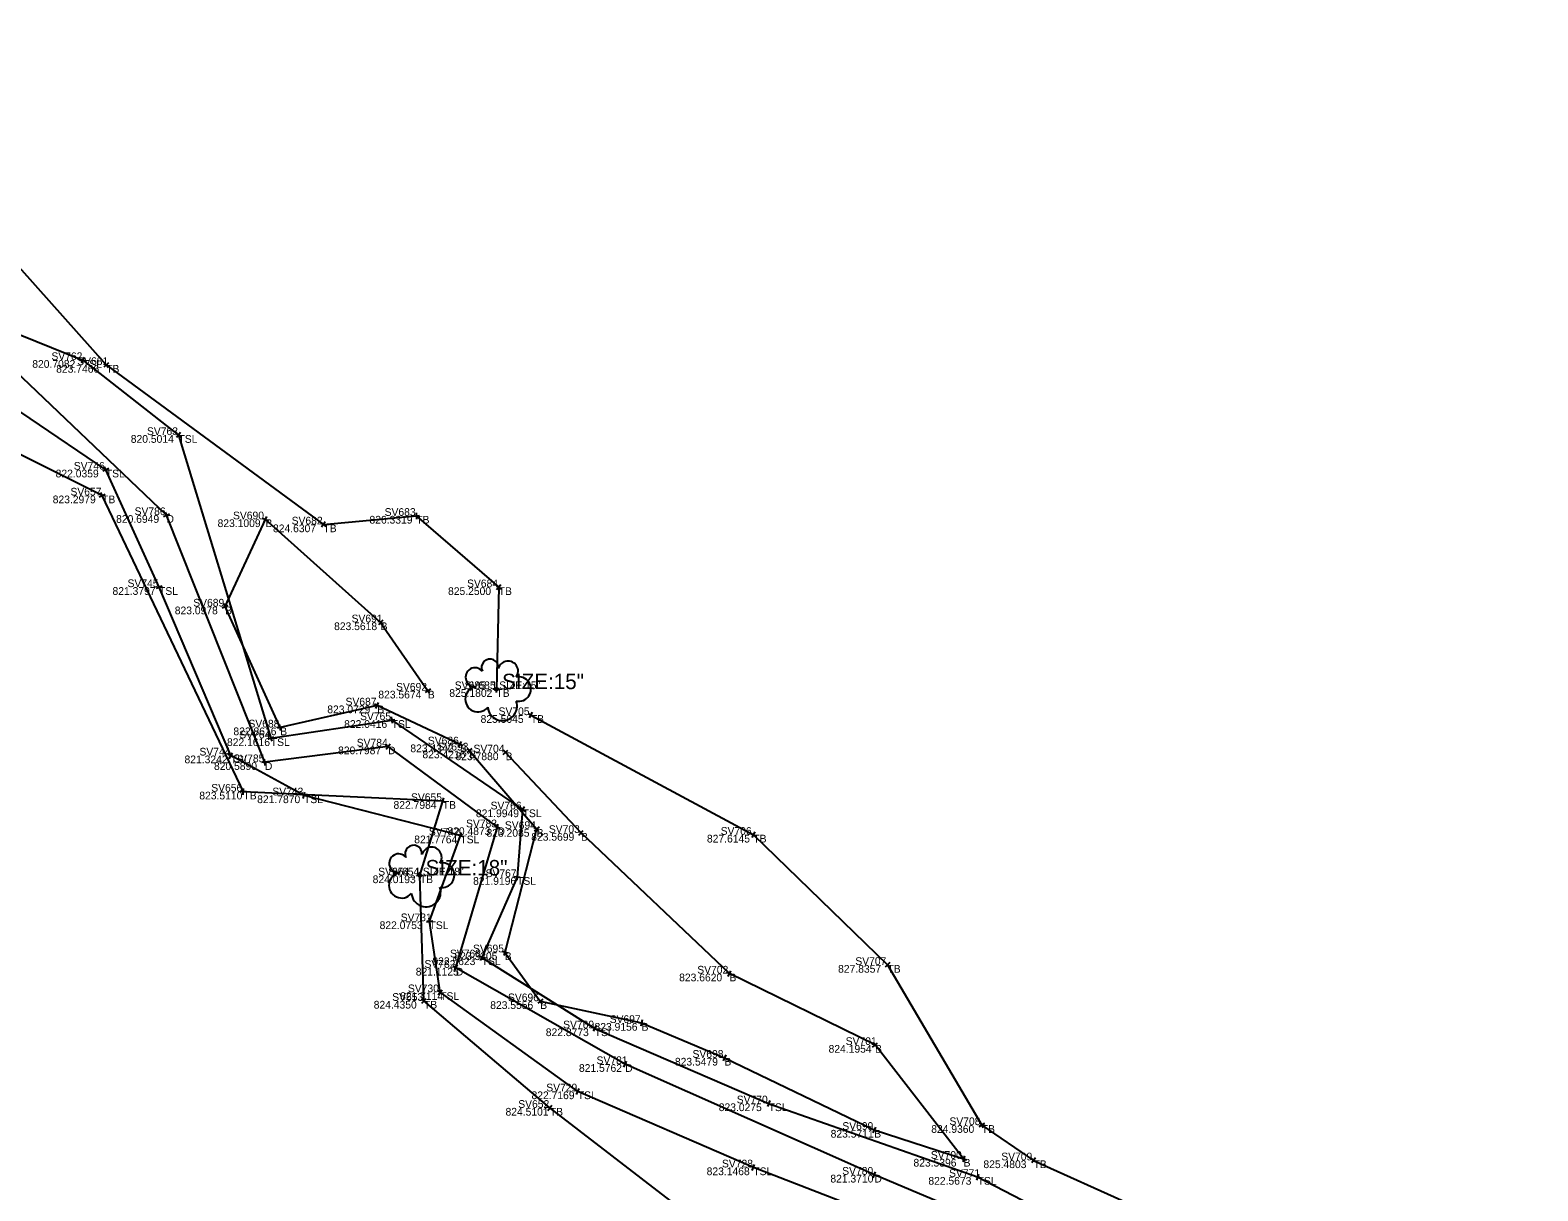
# Model space of a CAD drawing. Extents: x 1715717 to 1717046, y 393954 to 396000.
# Drawn here: x 1716379.9 to 1716497.2, y 394592.1 to 394682.3 of the extents above; entities that cross this region are included whole.
import ezdxf

# ---------------------------------------------------------------- set-up
doc = ezdxf.new("R2010")
doc.units = 0
for name, color, linetype in [('DR_X_Ditch', 7, 'Continuous'), ('SV_X_Break_Lines', 7, 'Continuous'), ('SV_X_Shot_Marker', 7, 'Continuous'), ('SV_X_Text_Comment', 7, 'Continuous'), ('SV_X_Text_Description', 7, 'Continuous'), ('SV_X_Text_Elevation', 7, 'Continuous'), ('SV_X_Text_Name', 7, 'Continuous'), ('SV_X_Toe_of_Slope', 7, 'Continuous'), ('SV_X_Top_of_Bank', 7, 'Continuous'), ('VG_X_Cells', 7, 'Continuous'), ('VG_X_Text', 7, 'Continuous')]:
    doc.layers.add(name, color=color, linetype=linetype)

msp = doc.modelspace()

# ---------------------------------------------------------------- linework, layer by layer
at = {"layer": 'DR_X_Ditch'}
msp.add_lwpolyline([(1716492.68, 394549.09), (1716480.2, 394562.11), (1716467.1, 394571.42), (1716461.87, 394586.51), (1716445.58, 394593.37), (1716426.21, 394601.97), (1716413.04, 394609.46), (1716416.27, 394620.38), (1716407.77, 394626.66), (1716398.19, 394625.44), (1716390.54, 394644.65), (1716377.65, 394656.94), (1716366.24, 394666.97), (1716357.54, 394672.43), (1716344.01, 394670.78), (1716331.46, 394670.98), (1716312.41, 394679.43), (1716306.34, 394675.77)], dxfattribs=at)
at = {"layer": 'SV_X_Break_Lines'}
for points in [[(1716413.36, 394626.82), (1716406.93, 394629.85), (1716399.38, 394628.14), (1716395.09, 394637.54), (1716398.24, 394644.32), (1716407.19, 394636.31), (1716410.86, 394631)], [(1716414.08, 394626.35), (1716419.32, 394620.25), (1716416.84, 394610.66), (1716419.6, 394606.86), (1716427.48, 394605.17), (1716433.92, 394602.46), (1716445.57, 394596.86), (1716452.52, 394594.61), (1716445.63, 394603.46), (1716434.31, 394609.01), (1716422.77, 394619.94), (1716416.91, 394626.2)]]:
    msp.add_lwpolyline(points, dxfattribs=at)
at = {"layer": 'SV_X_Shot_Marker'}
for p, q in [((1716384.13, 394656.93), (1716383.94, 394656.47)), ((1716383.81, 394656.79), (1716384.27, 394656.61)), ((1716384.04, 394656.7), (1716384.04, 394656.7)), ((1716386.04, 394656.49), (1716385.67, 394656.15)), ((1716385.69, 394656.5), (1716386.02, 394656.13)), ((1716385.85, 394656.32), (1716385.85, 394656.32)), ((1716391.28, 394651.02), (1716391.67, 394650.71)), ((1716391.63, 394651.06), (1716391.32, 394650.67)), ((1716391.47, 394650.87), (1716391.47, 394650.87)), ((1716385.59, 394648.08), (1716386.05, 394648.29)), ((1716385.92, 394647.96), (1716385.72, 394648.41)), ((1716385.82, 394648.18), (1716385.82, 394648.18)), ((1716385.64, 394645.95), (1716385.43, 394646.4)), ((1716385.31, 394646.07), (1716385.76, 394646.28)), ((1716385.53, 394646.17), (1716385.53, 394646.17)), ((1716390.31, 394644.55), (1716390.77, 394644.74)), ((1716390.63, 394644.41), (1716390.45, 394644.88)), ((1716390.54, 394644.65), (1716390.54, 394644.65)), ((1716398.01, 394644.42), (1716398.47, 394644.21)), ((1716398.13, 394644.09), (1716398.34, 394644.54)), ((1716398.24, 394644.32), (1716398.24, 394644.32)), ((1716402.53, 394644.06), (1716402.94, 394643.77)), ((1716402.88, 394644.12), (1716402.59, 394643.72)), ((1716409.71, 394644.56), (1716410.21, 394644.61)), ((1716409.94, 394644.83), (1716409.98, 394644.34)), ((1716409.96, 394644.59), (1716409.96, 394644.59)), ((1716402.74, 394643.92), (1716402.74, 394643.92)), ((1716389.73, 394638.96), (1716390.19, 394639.15)), ((1716390.06, 394638.82), (1716389.86, 394639.28)), ((1716389.96, 394639.05), (1716389.96, 394639.05)), ((1716416.18, 394639.2), (1716416.56, 394638.88)), ((1716416.53, 394639.23), (1716416.21, 394638.85)), ((1716416.37, 394639.04), (1716416.37, 394639.04)), ((1716394.87, 394637.44), (1716395.32, 394637.65)), ((1716395.2, 394637.31), (1716394.99, 394637.77)), ((1716395.09, 394637.54), (1716395.09, 394637.54)), ((1716407.01, 394636.48), (1716407.38, 394636.14)), ((1716407.36, 394636.49), (1716407.03, 394636.12)), ((1716407.19, 394636.31), (1716407.19, 394636.31)), ((1716411.07, 394631.15), (1716410.65, 394630.86)), ((1716410.72, 394631.21), (1716411, 394630.8)), ((1716416.44, 394631.11), (1716415.94, 394631.12)), ((1716416.19, 394631.37), (1716416.18, 394630.87)), ((1716416.19, 394631.12), (1716416.19, 394631.12)), ((1716407.15, 394629.74), (1716406.7, 394629.95)), ((1716406.82, 394629.62), (1716407.03, 394630.07)), ((1716410.86, 394631), (1716410.86, 394631)), ((1716406.93, 394629.85), (1716406.93, 394629.85)), ((1716407.8, 394628.68), (1716408.3, 394628.75)), ((1716408.01, 394628.96), (1716408.09, 394628.47)), ((1716418.65, 394629.22), (1716419.09, 394628.99)), ((1716418.98, 394629.32), (1716418.75, 394628.88)), ((1716418.87, 394629.1), (1716418.87, 394629.1)), ((1716399.62, 394628.19), (1716399.14, 394628.08)), ((1716399.44, 394627.89), (1716399.32, 394628.38)), ((1716399.38, 394628.14), (1716399.38, 394628.14)), ((1716408.05, 394628.71), (1716408.05, 394628.71)), ((1716398.89, 394627.38), (1716398.41, 394627.23)), ((1716398.57, 394627.54), (1716398.72, 394627.07)), ((1716398.65, 394627.3), (1716398.65, 394627.3)), ((1716407.97, 394626.52), (1716407.57, 394626.81)), ((1716407.62, 394626.46), (1716407.92, 394626.87)), ((1716407.77, 394626.66), (1716407.77, 394626.66)), ((1716413.59, 394626.71), (1716413.13, 394626.93)), ((1716413.25, 394626.59), (1716413.47, 394627.05)), ((1716413.36, 394626.82), (1716413.36, 394626.82)), ((1716414.27, 394626.51), (1716413.89, 394626.19)), ((1716413.92, 394626.54), (1716414.25, 394626.16)), ((1716395.76, 394625.84), (1716395.32, 394626.08)), ((1716395.42, 394625.74), (1716395.66, 394626.18)), ((1716395.54, 394625.96), (1716395.54, 394625.96)), ((1716398.43, 394625.47), (1716397.94, 394625.41)), ((1716398.22, 394625.19), (1716398.16, 394625.69)), ((1716398.19, 394625.44), (1716398.19, 394625.44)), ((1716414.08, 394626.35), (1716414.08, 394626.35)), ((1716416.72, 394626.03), (1716417.09, 394626.37)), ((1716417.08, 394626.01), (1716416.73, 394626.38)), ((1716416.91, 394626.2), (1716416.91, 394626.2)), ((1716396.77, 394623.14), (1716396.27, 394623.16)), ((1716396.51, 394622.9), (1716396.53, 394623.4)), ((1716396.52, 394623.15), (1716396.52, 394623.15)), ((1716401.47, 394622.8), (1716400.98, 394622.92)), ((1716401.16, 394622.62), (1716401.29, 394623.1)), ((1716401.23, 394622.86), (1716401.23, 394622.86)), ((1716411.78, 394622.49), (1716412.26, 394622.34)), ((1716411.95, 394622.18), (1716412.09, 394622.66)), ((1716412.02, 394622.42), (1716412.02, 394622.42)), ((1716418.03, 394621.91), (1716418.44, 394621.62)), ((1716418.37, 394621.97), (1716418.09, 394621.56)), ((1716418.23, 394621.77), (1716418.23, 394621.77)), ((1716416.2, 394620.15), (1716416.34, 394620.62)), ((1716413.16, 394619.83), (1716413.63, 394619.66)), ((1716413.31, 394619.51), (1716413.48, 394619.98)), ((1716413.39, 394619.74), (1716413.39, 394619.74)), ((1716416.03, 394620.46), (1716416.51, 394620.31)), ((1716416.27, 394620.38), (1716416.27, 394620.38)), ((1716419.51, 394620.41), (1716419.13, 394620.09)), ((1716419.15, 394620.44), (1716419.48, 394620.06)), ((1716419.32, 394620.25), (1716419.32, 394620.25)), ((1716422.95, 394619.77), (1716422.59, 394620.11)), ((1716422.6, 394619.76), (1716422.94, 394620.12)), ((1716422.77, 394619.94), (1716422.77, 394619.94)), ((1716435.95, 394619.92), (1716436.39, 394619.68)), ((1716436.29, 394620.02), (1716436.05, 394619.58)), ((1716436.17, 394619.8), (1716436.17, 394619.8)), ((1716409.99, 394616.64), (1716410.49, 394616.65)), ((1716410.25, 394616.39), (1716410.24, 394616.89)), ((1716410.24, 394616.64), (1716410.24, 394616.64)), ((1716418.05, 394616.49), (1716417.56, 394616.53)), ((1716417.83, 394616.76), (1716417.78, 394616.26)), ((1716417.8, 394616.51), (1716417.8, 394616.51)), ((1716410.75, 394613.04), (1716411.24, 394613.11)), ((1716411.03, 394612.83), (1716410.96, 394613.32)), ((1716410.99, 394613.08), (1716410.99, 394613.08)), ((1716415.27, 394610.17), (1716414.82, 394610.37)), ((1716415.15, 394610.5), (1716414.94, 394610.04)), ((1716415.05, 394610.27), (1716415.05, 394610.27)), ((1716417.09, 394610.6), (1716416.6, 394610.72)), ((1716416.91, 394610.9), (1716416.78, 394610.42)), ((1716416.84, 394610.66), (1716416.84, 394610.66)), ((1716413.26, 394609.33), (1716412.83, 394609.58)), ((1716412.92, 394609.24), (1716413.17, 394609.68)), ((1716413.04, 394609.46), (1716413.04, 394609.46)), ((1716434.53, 394608.9), (1716434.09, 394609.12)), ((1716434.2, 394608.78), (1716434.42, 394609.23)), ((1716434.31, 394609.01), (1716434.31, 394609.01)), ((1716446.42, 394609.86), (1716446.78, 394609.51)), ((1716446.78, 394609.86), (1716446.43, 394609.5)), ((1716446.6, 394609.68), (1716446.6, 394609.68)), ((1716412.02, 394607.42), (1716411.62, 394607.71)), ((1716411.67, 394607.36), (1716411.97, 394607.76)), ((1716410.75, 394606.73), (1716410.37, 394607.05)), ((1716410.4, 394606.7), (1716410.72, 394607.08)), ((1716410.56, 394606.89), (1716410.56, 394606.89)), ((1716411.82, 394607.56), (1716411.82, 394607.56)), ((1716419.8, 394607.01), (1716419.4, 394606.72)), ((1716419.45, 394607.07), (1716419.75, 394606.66)), ((1716419.6, 394606.86), (1716419.6, 394606.86)), ((1716427.53, 394605.41), (1716427.43, 394604.93)), ((1716423.63, 394604.89), (1716424.06, 394604.62)), ((1716423.98, 394604.97), (1716423.71, 394604.54)), ((1716423.84, 394604.75), (1716423.84, 394604.75)), ((1716427.23, 394605.22), (1716427.72, 394605.12)), ((1716427.48, 394605.17), (1716427.48, 394605.17)), ((1716445.43, 394603.3), (1716445.83, 394603.61)), ((1716445.79, 394603.26), (1716445.48, 394603.65)), ((1716445.63, 394603.46), (1716445.63, 394603.46)), ((1716426.44, 394601.87), (1716425.98, 394602.07)), ((1716426.11, 394601.74), (1716426.31, 394602.2)), ((1716426.21, 394601.97), (1716426.21, 394601.97)), ((1716433.69, 394602.56), (1716434.15, 394602.36)), ((1716434.02, 394602.69), (1716433.82, 394602.23)), ((1716433.92, 394602.46), (1716433.92, 394602.46)), ((1716422.75, 394599.75), (1716422.29, 394599.95)), ((1716422.42, 394599.62), (1716422.62, 394600.08)), ((1716422.52, 394599.85), (1716422.52, 394599.85)), ((1716420.55, 394598.42), (1716420.15, 394598.72)), ((1716420.2, 394598.37), (1716420.5, 394598.77)), ((1716420.35, 394598.57), (1716420.35, 394598.57)), ((1716437.14, 394599.02), (1716437.59, 394598.82)), ((1716437.46, 394599.15), (1716437.27, 394598.69)), ((1716437.36, 394598.92), (1716437.36, 394598.92)), ((1716454.14, 394597.35), (1716453.71, 394597.1)), ((1716453.8, 394597.44), (1716454.05, 394597.01)), ((1716453.93, 394597.23), (1716453.93, 394597.23)), ((1716445.34, 394596.96), (1716445.79, 394596.75)), ((1716445.67, 394597.08), (1716445.46, 394596.63)), ((1716445.57, 394596.86), (1716445.57, 394596.86)), ((1716452.6, 394594.85), (1716452.45, 394594.38)), ((1716436.4, 394593.85), (1716435.94, 394594.03)), ((1716436.08, 394593.71), (1716436.26, 394594.17)), ((1716436.17, 394593.94), (1716436.17, 394593.94)), ((1716445.48, 394593.14), (1716445.68, 394593.6)), ((1716452.29, 394594.69), (1716452.76, 394594.54)), ((1716452.52, 394594.61), (1716452.52, 394594.61)), ((1716457.76, 394594.63), (1716458.17, 394594.35)), ((1716458.1, 394594.7), (1716457.82, 394594.29)), ((1716457.96, 394594.49), (1716457.96, 394594.49)), ((1716445.81, 394593.27), (1716445.35, 394593.47)), ((1716445.58, 394593.37), (1716445.58, 394593.37)), ((1716453.37, 394593.28), (1716453.85, 394593.11)), ((1716453.69, 394593.43), (1716453.53, 394592.96)), ((1716453.61, 394593.2), (1716453.61, 394593.2))]:
    msp.add_line(p, q, dxfattribs=at)
at = {"layer": 'SV_X_Toe_of_Slope'}
for points in [[(1716303.13, 394676.12), (1716303.18, 394677.2), (1716311.54, 394681.81), (1716329.16, 394673.95), (1716341.86, 394674.93), (1716356.44, 394675.25), (1716363.05, 394673.36), (1716375.34, 394660.19), (1716384.04, 394656.7), (1716391.47, 394650.87), (1716398.65, 394627.3), (1716408.05, 394628.71), (1716418.23, 394621.77), (1716417.8, 394616.51), (1716415.05, 394610.27), (1716423.84, 394604.75), (1716437.36, 394598.92), (1716453.61, 394593.2), (1716464.69, 394587.45), (1716470.07, 394570.92), (1716482.89, 394564.22), (1716497.17, 394548.51)], [(1716492.21, 394544.75), (1716479.21, 394559.3), (1716468.9, 394566.34), (1716462.82, 394568.54), (1716461.69, 394581.64), (1716457.71, 394585.59), (1716436.17, 394593.94), (1716422.52, 394599.85), (1716411.82, 394607.56), (1716410.99, 394613.08), (1716413.39, 394619.74), (1716401.23, 394622.86), (1716395.54, 394625.96), (1716389.96, 394639.05), (1716385.82, 394648.18), (1716374.04, 394656.15), (1716364.57, 394663.16), (1716344.14, 394667.57), (1716337.85, 394662.89), (1716323.14, 394673.47), (1716312.25, 394677.47), (1716306.94, 394672.93)]]:
    msp.add_lwpolyline(points, dxfattribs=at)
at = {"layer": 'SV_X_Top_of_Bank'}
for points in [[(1716302.36, 394677.2), (1716304.97, 394679.78), (1716306.46, 394679.8), (1716307.19, 394680.14), (1716308.53, 394680.9), (1716311.46, 394682.35), (1716327.75, 394677.72), (1716357.29, 394676.29), (1716365.57, 394674.61), (1716374.78, 394668.71), (1716385.85, 394656.32), (1716402.74, 394643.92), (1716409.96, 394644.59), (1716416.37, 394639.04), (1716416.19, 394631.12)], [(1716489.25, 394541.62), (1716463.67, 394564.39), (1716459.39, 394581.53), (1716456.21, 394582.39), (1716449.56, 394581.93), (1716437.14, 394585.64), (1716420.35, 394598.57), (1716410.56, 394606.89), (1716410.24, 394616.64), (1716412.02, 394622.42), (1716396.52, 394623.15), (1716385.53, 394646.17), (1716369.09, 394654.4), (1716345.13, 394665.89), (1716337.04, 394662.29), (1716323.94, 394670.44), (1716313.49, 394675.73), (1716309.72, 394673.53), (1716308, 394672.9), (1716307.03, 394672.42)], [(1716418.87, 394629.1), (1716436.17, 394619.8), (1716446.6, 394609.68), (1716453.93, 394597.23), (1716457.96, 394594.49), (1716465.56, 394591.05), (1716485.61, 394568.71), (1716486.15, 394565.48), (1716488.85, 394563.28)]]:
    msp.add_lwpolyline(points, dxfattribs=at)
at = {"layer": 'VG_X_Cells'}
for centre in [(1716416.19, 394631.12), (1716410.24, 394616.64)]:
    msp.add_circle(centre, 0.12, dxfattribs=at)
for centre, radius, start, end in [((1716415.69, 394632.8), 0.658, 354.0047, 205.9741), ((1716414.53, 394632.05), 0.735, 39.0625, 279.5412), ((1716417.1, 394632.53), 0.776, 323.83, 165.0376), ((1716414.76, 394630.34), 0.987, 96.1722, 320.5737), ((1716417.92, 394631.13), 0.957, 259.1453, 101.4596), ((1716416.66, 394629.81), 1.14, 184.9476, 19.4572), ((1716408.59, 394617.58), 0.735, 39.0625, 279.5412), ((1716409.75, 394618.33), 0.658, 354.0047, 205.9741), ((1716411.16, 394618.06), 0.776, 323.83, 165.0376), ((1716411.97, 394616.66), 0.957, 259.1453, 101.4596), ((1716408.82, 394615.87), 0.987, 96.1722, 320.5737), ((1716410.72, 394615.34), 1.14, 184.9476, 19.4572)]:
    msp.add_arc(centre, radius, start, end, dxfattribs=at)

# ---------------------------------------------------------------- texts
at = {"layer": 'SV_X_Text_Comment'}
for s, p in [('TSL', (1716384.04, 394656.1)), ('TB', (1716385.85, 394655.72)), ('TSL', (1716391.47, 394650.27)), ('TSL', (1716385.82, 394647.58)), ('TB', (1716385.53, 394645.57)), ('D', (1716390.54, 394644.05)), ('B', (1716398.24, 394643.72)), ('TB', (1716409.96, 394643.99)), ('TB', (1716402.74, 394643.32)), ('TSL', (1716389.96, 394638.45)), ('TB', (1716416.37, 394638.44)), ('B', (1716395.09, 394636.94)), ('B', (1716407.19, 394635.71)), ('TB', (1716416.19, 394630.52)), ('T', (1716416.19, 394630.52)), ('B', (1716410.86, 394630.4)), ('B', (1716406.93, 394629.25)), ('TB', (1716418.87, 394628.5)), ('B', (1716399.38, 394627.54)), ('TSL', (1716408.05, 394628.11)), ('TSL', (1716398.65, 394626.7)), ('D', (1716407.77, 394626.06)), ('B', (1716413.36, 394626.22)), ('TSL', (1716395.54, 394625.36)), ('D', (1716398.19, 394624.84)), ('B', (1716414.08, 394625.75)), ('B', (1716416.91, 394625.6)), ('TB', (1716396.52, 394622.55)), ('TSL', (1716401.23, 394622.26)), ('TB', (1716412.02, 394621.82)), ('TSL', (1716418.23, 394621.17)), ('TSL', (1716413.39, 394619.14)), ('D', (1716416.27, 394619.78)), ('B', (1716419.32, 394619.65)), ('B', (1716422.77, 394619.34)), ('TB', (1716436.17, 394619.2)), ('TB', (1716410.24, 394616.04)), ('T', (1716410.24, 394616.04)), ('TSL', (1716417.8, 394615.91)), ('TSL', (1716410.99, 394612.47)), ('TSL', (1716415.05, 394609.67)), ('B', (1716416.84, 394610.06)), ('D', (1716413.04, 394608.86)), ('B', (1716434.31, 394608.41)), ('TB', (1716446.6, 394609.08)), ('TB', (1716410.56, 394606.29)), ('TSL', (1716411.82, 394606.96)), ('B', (1716419.6, 394606.26)), ('TSL', (1716423.84, 394604.15)), ('B', (1716427.48, 394604.57)), ('B', (1716445.63, 394602.86)), ('D', (1716426.21, 394601.37)), ('B', (1716433.92, 394601.86)), ('TSL', (1716422.52, 394599.25)), ('TB', (1716420.35, 394597.97)), ('TSL', (1716437.36, 394598.32)), ('TB', (1716453.93, 394596.63)), ('B', (1716445.57, 394596.26)), ('TSL', (1716436.17, 394593.34)), ('B', (1716452.52, 394594.01)), ('TB', (1716457.96, 394593.89)), ('D', (1716445.58, 394592.77)), ('TSL', (1716453.61, 394592.6))]:
    msp.add_text(s, height=0.6, dxfattribs=at).set_placement(p)
at = {"layer": 'SV_X_Text_Description'}
for s, p in [(' SIZE:15" ', (1716416.19, 394631.12)), (' SIZE:18" ', (1716410.24, 394616.64))]:
    msp.add_text(s, height=0.6, dxfattribs=at).set_placement(p)
at = {"layer": 'SV_X_Text_Elevation'}
for s, p in [('820.7082', (1716380.1, 394656.1)), ('823.7466', (1716381.96, 394655.72)), ('820.5014', (1716387.76, 394650.27)), ('822.0359', (1716381.92, 394647.58)), ('823.2979', (1716381.69, 394645.57)), ('820.6949', (1716386.62, 394644.05)), ('823.1009', (1716394.51, 394643.72)), ('826.3319', (1716406.32, 394643.99)), ('824.6307', (1716398.82, 394643.32)), ('821.3797', (1716386.34, 394638.45)), ('825.2500', (1716412.43, 394638.44)), ('823.0978', (1716391.18, 394636.94)), ('823.5618', (1716403.57, 394635.71)), ('825.1802', (1716412.53, 394630.52)), ('825.1802', (1716412.53, 394630.52)), ('823.5674', (1716407.01, 394630.4)), ('823.0729', (1716403.04, 394629.25)), ('825.5045', (1716414.96, 394628.5)), ('822.8616', (1716395.74, 394627.54)), ('822.0416', (1716404.35, 394628.11)), ('822.1616', (1716395.24, 394626.7)), ('820.7987', (1716403.88, 394626.06)), ('823.4342', (1716409.5, 394626.22)), ('821.3242', (1716391.94, 394625.36)), ('820.5890', (1716394.23, 394624.84)), ('823.4216', (1716410.44, 394625.75)), ('823.7880', (1716413.01, 394625.6)), ('823.5110', (1716393.09, 394622.55)), ('821.7870', (1716397.59, 394622.26)), ('822.7984', (1716408.19, 394621.82)), ('821.9949', (1716414.6, 394621.17)), ('821.7764', (1716409.8, 394619.14)), ('820.4873', (1716412.38, 394619.78)), ('823.2085', (1716415.42, 394619.65)), ('823.5699', (1716418.9, 394619.34)), ('827.6145', (1716432.56, 394619.2)), ('824.0193', (1716406.57, 394616.04)), ('824.0193', (1716406.57, 394616.04)), ('821.9196', (1716414.38, 394615.91)), ('822.0753', (1716407.11, 394612.47)), ('822.5623', (1716411.21, 394609.67)), ('823.3305', (1716412.92, 394610.06)), ('821.1125', (1716409.92, 394608.86)), ('823.6620', (1716430.4, 394608.41)), ('827.8357', (1716442.76, 394609.08)), ('824.4350', (1716406.65, 394606.29)), ('821.7114', (1716408.7, 394606.96)), ('823.5556', (1716415.71, 394606.26)), ('822.8773', (1716420.03, 394604.15)), ('823.9156', (1716423.82, 394604.57)), ('824.1954', (1716442.02, 394602.86)), ('821.5762', (1716422.61, 394601.37)), ('823.5479', (1716430.07, 394601.86)), ('822.7169', (1716418.92, 394599.25)), ('824.5101', (1716416.9, 394597.97)), ('823.0275', (1716433.48, 394598.32)), ('824.9360', (1716450, 394596.63)), ('823.5711', (1716442.18, 394596.26)), ('823.1468', (1716432.54, 394593.34)), ('823.5396', (1716448.62, 394594.01)), ('825.4803', (1716454.06, 394593.89)), ('821.3710', (1716442.16, 394592.77)), ('822.5673', (1716449.78, 394592.6))]:
    msp.add_text(s, height=0.6, dxfattribs=at).set_placement(p)
at = {"layer": 'SV_X_Text_Name'}
for s, p in [('SV762', (1716381.59, 394656.7)), ('SV681', (1716383.6, 394656.32)), ('SV763', (1716389.02, 394650.87)), ('SV746', (1716383.33, 394648.18)), ('SV657', (1716383.07, 394646.17)), ('SV786', (1716388.06, 394644.65)), ('SV683', (1716407.5, 394644.59)), ('SV690', (1716395.71, 394644.32)), ('SV682', (1716400.27, 394643.92)), ('SV745', (1716387.51, 394639.05)), ('SV684', (1716413.91, 394639.04)), ('SV689', (1716392.62, 394637.54)), ('SV691', (1716404.93, 394636.31)), ('SV692', (1716408.39, 394631)), ('SV685_1', (1716412.95, 394631.12)), ('SV685', (1716413.72, 394631.12)), ('SV687', (1716404.46, 394629.85)), ('SV688', (1716396.91, 394628.14)), ('SV765', (1716405.59, 394628.71)), ('SV705', (1716416.36, 394629.1)), ('SV764', (1716396.2, 394627.3)), ('SV744', (1716393.1, 394625.96)), ('SV784', (1716405.33, 394626.66)), ('SV686', (1716410.86, 394626.82)), ('SV693', (1716411.61, 394626.35)), ('SV704', (1716414.41, 394626.2)), ('SV785', (1716395.74, 394625.44)), ('SV656', (1716394.02, 394623.15)), ('SV743', (1716398.77, 394622.86)), ('SV655', (1716409.55, 394622.42)), ('SV766', (1716415.74, 394621.77)), ('SV783', (1716413.83, 394620.38)), ('SV694', (1716416.85, 394620.25)), ('SV703', (1716420.27, 394619.94)), ('SV742', (1716410.94, 394619.74)), ('SV706', (1716433.63, 394619.8)), ('SV654_1', (1716407, 394616.64)), ('SV654', (1716407.78, 394616.64)), ('SV767', (1716415.35, 394616.51)), ('SV731', (1716408.75, 394613.08)), ('SV695', (1716414.37, 394610.66)), ('SV782', (1716410.6, 394609.46)), ('SV768', (1716412.58, 394610.27)), ('SV707', (1716444.1, 394609.68)), ('SV702', (1716431.81, 394609.01)), ('SV730', (1716409.31, 394607.56)), ('SV653', (1716408.09, 394606.89)), ('SV696', (1716417.09, 394606.86)), ('SV769', (1716421.38, 394604.75)), ('SV697', (1716425, 394605.17)), ('SV698', (1716431.44, 394602.46)), ('SV701', (1716443.35, 394603.46)), ('SV781', (1716423.98, 394601.97)), ('SV729', (1716420.07, 394599.85)), ('SV770', (1716434.88, 394598.92)), ('SV652', (1716417.89, 394598.57)), ('SV699', (1716443.09, 394596.86)), ('SV708', (1716451.42, 394597.23)), ('SV700', (1716449.97, 394594.61)), ('SV709', (1716455.45, 394594.49)), ('SV728', (1716433.73, 394593.94)), ('SV780', (1716443.08, 394593.37)), ('SV771', (1716451.39, 394593.2))]:
    msp.add_text(s, height=0.6, dxfattribs=at).set_placement(p)
at = {"layer": 'VG_X_Text'}
for s, p in [(' SIZE:15" ', (1716416.19, 394631.12)), (' SIZE:18" ', (1716410.24, 394616.64))]:
    msp.add_text(s, height=1.2, dxfattribs=at).set_placement(p)

doc.saveas('drawing.dxf')
